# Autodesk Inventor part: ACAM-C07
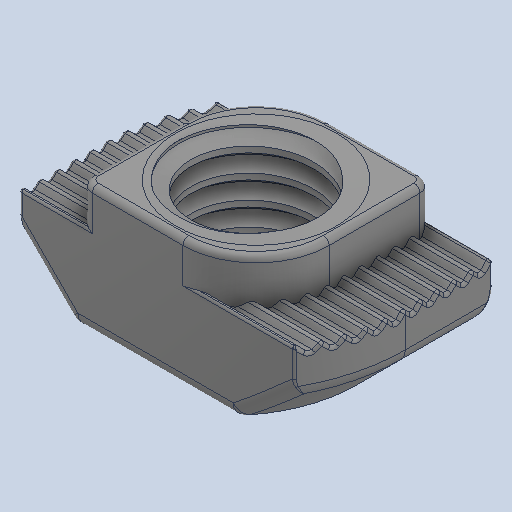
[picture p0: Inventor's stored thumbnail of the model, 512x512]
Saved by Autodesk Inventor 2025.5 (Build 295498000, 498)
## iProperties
Created: 2025-11
Part Number: ACAM-C07
Material: Steel
Description: Tuerca T M5 — modelo 2020
Document SubType Name: Modeling
Designer: Luis M
Density: 7.85 g/cm^3
Appearance: Valor por defecto
Sending System: Autodesk Translation Framework v14.21.0.0
Preprocessor: ST-DEVELOPER v20.1
Material_BOM: Por especificar
Proceso_BOM: Comercial
Title: T NUT M5 2020.step
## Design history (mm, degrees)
feature "Body1"
node "Sólido1"
